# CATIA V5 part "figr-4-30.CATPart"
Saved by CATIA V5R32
Part number: Part1
Bounding box of the stored display mesh (mm): x -89.975 to 89.975, y -89.975 to 89.975, z 0 to 190
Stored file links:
  D:\PROJECTS\Project 2022\CATIA V5 6R 2022\Resources\Part Files\c04_catia_v5_6r2022_prt\figr-4-30.CATPart
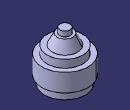
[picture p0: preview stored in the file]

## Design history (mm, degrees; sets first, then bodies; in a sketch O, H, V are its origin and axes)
Set1
  Line1 "Y Axis": stored without definition
  Line2 "Y Axis": stored without definition
  Line3 "X Axis": stored without definition
  Line4 "Z Axis": stored without definition
Body1 (main body)
  Sketch1 on yz-plane, origin (0, 0, 0), H (0, 1, 0), V (0, 0, 1)
    line L1 (0, 0) -> (80, 0)
    line L2 (80, 0) -> (80, 30)
    line L3 (80, 30) -> (90, 30)
    line L4 (90, 30) -> (90, 100)
    line L5 (90, 100) -> (70, 100)
    line L6 (70, 100) -> (70, 130)
    line L7 (70, 130) -> (50, 130)
    line L8 (50, 130) -> (30, 170)
    line L9 (30, 170) -> (20, 170)
    line L10 (20, 170) -> (20, 190)
    line L11 (20, 190) -> (0, 190)
    point P11 (0, 190)
    line L12 (0, 190) -> (0, 0)
    axis line L13 (0, -40) -> (0, 230)
    point P12 (0, -40)
    point P13 (0, 230)
    horizontal: L1 H, L3 H, L5 H, L7 H, L9 H, L11 H
    vertical: L2 V, L4 V, L6 V, L10 V, L12 V, L13 V
    coincidence: P11 V, P12 V, P13 L8
  Shaft1: profile Sketch1, axis Sketch1.L13, angle 360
